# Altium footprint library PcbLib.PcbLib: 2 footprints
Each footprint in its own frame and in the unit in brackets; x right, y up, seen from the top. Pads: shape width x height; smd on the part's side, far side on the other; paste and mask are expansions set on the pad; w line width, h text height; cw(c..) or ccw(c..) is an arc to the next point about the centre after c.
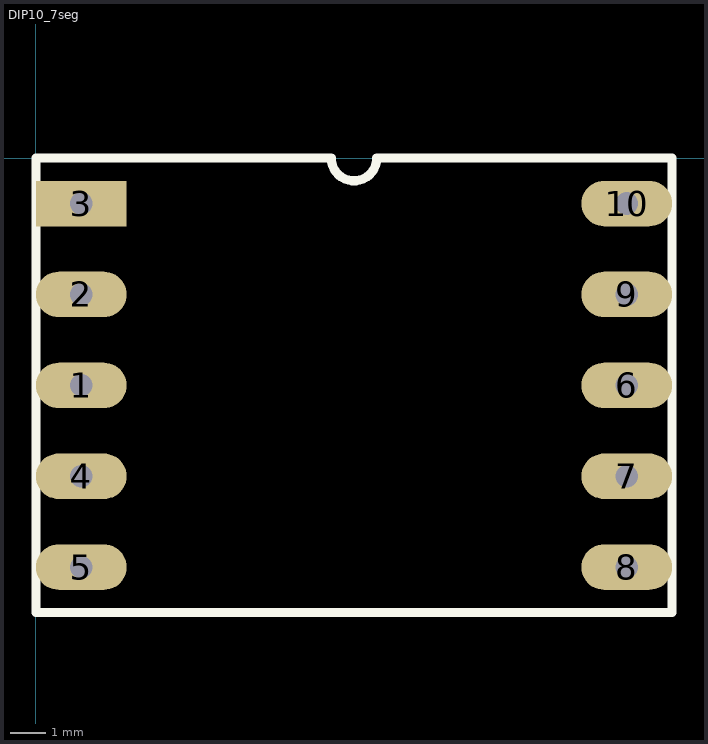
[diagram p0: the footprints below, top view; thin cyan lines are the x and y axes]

## DIP10_7seg [mil]
pads (10):
  oval 100x50 hole 25: 1(50,-250) 2(50,-150) 4(50,-350) 5(50,-450) 6(650,-250) 7(650,-350) 8(650,-450) 9(650,-150) 10(650,-50)
  rect 100x50 hole 25: 3(50,-50)
Top Overlay:
  lines w10: 0,-500 0,0 325,0 ccw(c350,0) 375,0 700,0 700,-500 0,-500

## PCBComponent_1 [mil]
